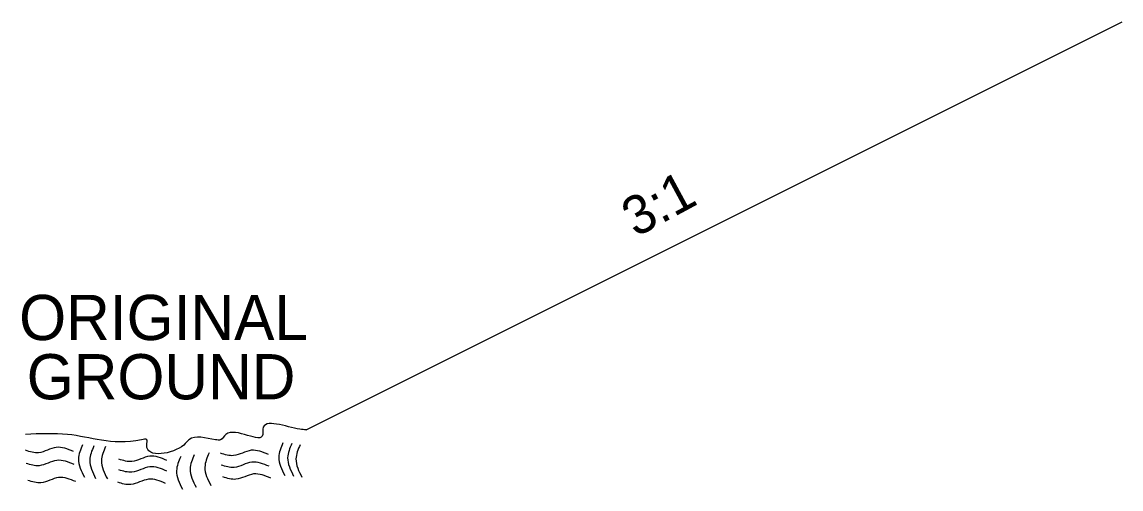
# Model space of a CAD drawing. Extents: x 1593595 to 1594166, y 741647 to 741854.
# Drawn here: x 1594031.58 to 1594051.46, y 741725.35 to 741733.8 of the extents above; entities that cross this region are included whole.
import ezdxf

# ---------------------------------------------------------------- set-up
doc = ezdxf.new("R2010")
doc.units = 0
for name, color, linetype in [('Old_Level_1', 7, 'Continuous'), ('Old_Level_2', 7, 'Continuous'), ('Old_Level_3', 7, 'Continuous')]:
    doc.layers.add(name, color=color, linetype=linetype)

msp = doc.modelspace()

# ---------------------------------------------------------------- linework, layer by layer
at = {"layer": 'Old_Level_1'}
msp.add_line((1594036.719, 741726.422), (1594051.483, 741733.804), dxfattribs=at)
at = {"layer": 'Old_Level_2'}
for points in [[(1594036.719, 741726.422), (1594036.605, 741726.434), (1594035.937, 741726.434), (1594035.937, 741726.339), (1594035.269, 741726.339), (1594035.173, 741726.243), (1594035.078, 741726.243), (1594034.601, 741726.243), (1594034.505, 741726.148), (1594033.837, 741726.148), (1594033.837, 741726.243), (1594033.742, 741726.243), (1594032.405, 741726.339), (1594031.644, 741726.339)], [(1594036.3, 741726.185), (1594036.226, 741725.929), (1594036.333, 741725.597)], [(1594032.51, 741726.03), (1594032.2, 741726.105), (1594031.88, 741726.009), (1594031.644, 741726.052)], [(1594032.676, 741726.153), (1594032.601, 741725.897), (1594032.708, 741725.565)], [(1594032.879, 741726.132), (1594032.805, 741725.875), (1594032.912, 741725.544)], [(1594033.093, 741726.121), (1594033.018, 741725.865), (1594033.125, 741725.533)], [(1594034.964, 741726.004), (1594034.889, 741725.747), (1594034.996, 741725.416)], [(1594036.038, 741725.977), (1594035.728, 741726.052), (1594035.408, 741725.956), (1594035.173, 741725.998)], [(1594036.461, 741726.175), (1594036.386, 741725.918), (1594036.493, 741725.587)], [(1594036.611, 741726.153), (1594036.536, 741725.897), (1594036.643, 741725.565)], [(1594032.521, 741725.795), (1594032.211, 741725.87), (1594031.89, 741725.774), (1594031.655, 741725.816)], [(1594034.2, 741725.87), (1594033.89, 741725.945), (1594033.569, 741725.849), (1594033.334, 741725.891)], [(1594034.451, 741725.939), (1594034.376, 741725.683), (1594034.483, 741725.351)], [(1594034.697, 741725.972), (1594034.622, 741725.715), (1594034.729, 741725.383)], [(1594036.049, 741725.763), (1594035.739, 741725.838), (1594035.418, 741725.742), (1594035.183, 741725.784)], [(1594034.2, 741725.677), (1594033.89, 741725.752), (1594033.569, 741725.656), (1594033.334, 741725.699)], [(1594036.081, 741725.549), (1594035.771, 741725.624), (1594035.45, 741725.528), (1594035.215, 741725.571)], [(1594032.553, 741725.485), (1594032.243, 741725.56), (1594031.922, 741725.464), (1594031.687, 741725.506)], [(1594034.178, 741725.453), (1594033.868, 741725.528), (1594033.548, 741725.432), (1594033.312, 741725.474)]]:
    msp.add_spline(points, degree=3, dxfattribs=at)

# ---------------------------------------------------------------- texts
at = {"layer": 'Old_Level_1'}
for s, p in [('ORIGINAL', (1594031.528, 741728.047)), ('GROUND', (1594031.665, 741726.975))]:
    msp.add_text(s, height=0.8181, dxfattribs=at).set_placement(p)
at = {"layer": 'Old_Level_3'}
msp.add_text('3:1', height=0.7025, rotation=28.3904, dxfattribs=at).set_placement((1594042.684, 741729.898))

doc.saveas('drawing.dxf')
